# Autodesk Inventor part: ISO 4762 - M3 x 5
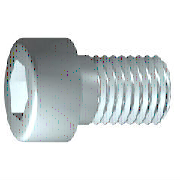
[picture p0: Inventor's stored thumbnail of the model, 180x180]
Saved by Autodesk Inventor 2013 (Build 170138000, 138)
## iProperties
Created: 2012-02
Part Number: ISO 4762 - M3 x 5
Material: Edelstahl, 440C
Description: Innensechskantschraube
Document SubType Name: Modeling
Standard: ISO 4762
Designer: rYan
Standard Revision: 1998
Standards Organization: DIN
Language: de-DE
Size Designation: M3 x 5
Categories: <MemberInstance><Categories><Category DisplayName="Verbindungselemente" InternalName="e4da775c-781d-43d5-af7c-5136215cf5a6" Mnemonic="FSTN"><Category DisplayNam
Density: 7.75 g/cm^3
IsCustomPart: 0
Author: rYan
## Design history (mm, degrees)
sketch "Skizze1"
  geometry: L1 (-0.867, 0)-(5, 0); L2 (5, 0)-(5, 1.5); L3 (5, 1.5)-(1.25, 1.5); L4 (1.25, 1.5)-(0.943, 1.5); L5 (0.943, 1.5)-(0, 1.5); L6 (0, 1.5)-(0, 2.75); L7 (0, 2.75)-(-3, 2.75); L8 (-3, 2.75)-(-3, 1.443); L9 (-3, 1.443)-(-1.7, 1.443); L10 (-1.7, 1.443)-(-0.867, 0); L11 (-4.6, 0)-(6.6, 0) reference; L12 (0, -0.55)-(0, 3.3) reference; L13 (1.25, 1.5)-(0, 1.5)
  constraints: 22 end point, 6 parallel, 2 collinear, 2 perpendicular, 1 horizontal, 1 point on line
  dimensions: "d1" = 3.75 distance from line of L3.end L2 (= GEL); "d2" = 0.30683 distance of L4.end L3.end (computed from GAL); "d3" = 3 distance between parallel lines of L8 L6 (= KOH); "d4" = 1.3 distance of L8.end L9.end (= INTI); "d5" = 60 deg angle of L10 L1; "d6" = 3 diameter of L3 L1 (= GD); "d7" = 3 diameter of L5 L1 (= BDM); "d8" = 2.88675 diameter of L9 L1 (= 1.1547 x SW); "d9" = 5.5 diameter of L7 L1 (= KOD); "d26" = 5 distance between parallel lines of L12 L2 (= NLG)
revolve "Körper" sketch "Skizze1" stored, may be unused: angle "d10" = 90 deg
sketch "Skizze2"
  geometry: L1 (0, -3.85)-(0, 3.85) reference; L2 (-3.85, 0)-(3.85, 0) reference; L3 (1.443, 0)-(0.722, -1.25); L4 (0.722, -1.25)-(-0.722, -1.25); L5 (-0.722, -1.25)-(-1.443, 0); L6 (-1.443, 0)-(-0.722, 1.25); L7 (-0.722, 1.25)-(0.722, 1.25); L8 (0.722, 1.25)-(1.443, 0); 2 further points
  constraints: 12 end point, 1 coincident, 1 horizontal alignment, 1 point on line, 12 other
extrude "Loch" join sketch "Skizze2" stored distance "d11" = 10; taper "d12" = 0 deg
workplane "Work Plane1"
fillet "Fillet2" dims "d30" = 0.1 (= R)
body "Solid1"
fillet "Rundung1" dims "d17" = 0.3 (= RR)
feature "Gewinde" dims "d13" = 3.75 (= GEL), "d14" = 0
chamfer "Fase1" distance "d15" = 0.30673 (= -0.5 x SPD + 0.5 x GD); stored, may be unused: second distance "d16" = 0.30673 (= GUL), angle "d27" = 45 deg
other parameters: "GD" = 3 [user parameter; used in 2 equation terms], "NLG" = 5 [user parameter; used in 1 equation term], "GEL" = 3.75 [user parameter; used in 2 equation terms], "KOD" = 5.5 [user parameter; used in 1 equation term], "KOH" = 3 [user parameter; used in 1 equation term], "INTI" = 1.3 [user parameter; used in 1 equation term], "GAL" = 0.30673 (= 0.61345 x PTC) [user parameter; used in 1 equation term], "GUL" = 0.30673 (= 0.61345 x PTC) [user parameter; used in 1 equation term], "BDM" = 3 (= NND) [user parameter; used in 1 equation term], "SW" = 2.5 [user parameter; used in 2 equation terms], "RR" = 0.3 [user parameter; used in 1 equation term], "SPD" = 2.38655 (= NND - 1.2269 x PTC) [user parameter; used in 1 equation term], "d19" = 0, "d28" = 0, "d29" = 0, "R" = 0.1 [user parameter; used in 1 equation term], "TOA" = 30 deg [user parameter], "GD1" = 2.38655 (= THREADDIA - 1.2269 x PTC) [user parameter], "THREADDIA" = 3 [user parameter; used in 1 equation term], "FAWI" = 45 deg [user parameter], "PTC" = 0.5 [user parameter; used in 5 equation terms], "NND" = 3 [user parameter; used in 2 equation terms], "E0" = 2.8875 (= 1.155 x SW) [user parameter]
